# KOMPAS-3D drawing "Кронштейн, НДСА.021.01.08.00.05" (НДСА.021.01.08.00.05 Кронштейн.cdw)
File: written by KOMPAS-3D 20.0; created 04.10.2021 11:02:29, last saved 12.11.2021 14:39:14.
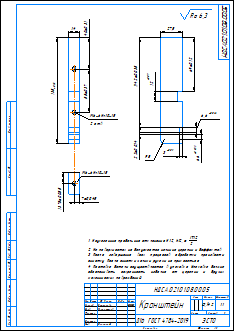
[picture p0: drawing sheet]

Sheet 1: A3, portrait

Document properties: Полное имя файла: C:\Users\korychko\Desktop\PLM\НДСА.021.01.08.00.05 Кронштейн.cdw; Автор: adminzsc; Параметр неуказанной шероховатости: Ra 6,3; PLM_CDWXDTO: <item xmlns="http://appius.ru/pdm" xmlns:xs="http://www.w3.org/2001/XMLSchema" xmlns:xsi="http://www.w3.org/2001/XMLSchema-instance" xsi:type="item">  <element xmlns:d2p1="http://v8.1c.ru/8.1/data/enterprise/current-config" xsi:type="d2p1:CatalogRef.aps_Элемен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; PDM_DOCXDTO: <item xmlns="http://appius.ru/pdm" xmlns:xs="http://www.w3.org/2001/XMLSchema" xmlns:xsi="http://www.w3.org/2001/XMLSchema-instance" xsi:type="item">  <element xmlns:d2p1="http://v8.1c.ru/8.1/data/enterprise/current-config" xsi:type="d2p1:CatalogRef.aps_Элемен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; PDM_ITEMXDTO: <item xmlns="http://appius.ru/pdm" xmlns:xs="http://www.w3.org/2001/XMLSchema" xmlns:xsi="http://www.w3.org/2001/XMLSchema-instance" xsi:type="item">  <element xmlns:d2p1="http://v8.1c.ru/8.1/data/enterprise/current-config" xsi:type="d2p1:CatalogRef.aps_Элемен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; Масса: 0.13847; PDM_DRAWINGXDTO: <item xmlns="http://appius.ru/pdm" xmlns:xs="http://www.w3.org/2001/XMLSchema" xmlns:xsi="http://www.w3.org/2001/XMLSchema-instance" xsi:type="item">  <element xmlns:d2p1="http://v8.1c.ru/8.1/data/enterprise/current-config" xsi:type="d2p1:CatalogRef.aps_Элемен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

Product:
- Part/product: Кронштейн  | designation НДСА.021.01.08.00.05
    Материал: Д16  ГОСТ 4784-2019 (density 2800 kg/m3)
    Масса: 0.138473
    additional columns: <item xmlns="http://appius.ru/pdm" xmlns:xs="http://www.w3.org/2001/XMLSchema" x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; <item xmlns="http://appius.ru/pdm" xmlns:xs="http://www.w3.org/2001/XMLSchema" x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; <item xmlns="http://appius.ru/pdm" xmlns:xs="http://www.w3.org/2001/XMLSchema" x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
    source file: НДСА.021.01.08.00.05 Кронштейн.cdw

Title block, sheet 1: Наименование: Кронштейн; designation: НДСА.021.01.08.00.05; Материал: Д16  ГОСТ 4784-2019; Масса: 0,14 г; Количество листов документа: 1; organisation: ЭСТО; Форматы листов документа: A3; stored path: C:\Users\vasilyeva\Desktop\PM_APPIUS\НДСА.021.01.08.00.05 Кронштейн.cdw; Разработал: Васильева; Проверил: Горностаев; Утвердил: Белецкий; Разработал, date: 04.10.2021

Views: Вид 1, Спереди, Проекционный вид 2, Проекционный вид 3
Referenced files in C:\Users\vasilyeva\Desktop\PM_APPIUS\: НДСА.021.01.08.00.05 Кронштейн.m3d
Referenced files in C:\Users\korychko\Desktop\PLM\: НДСА.021.01.08.00.05 Кронштейн.m3d
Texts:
  JS11
  Ra 6,3
  НДСА.021.01.08.00.05 Кронштейн
Dimensions and other numbers on the sheet: 14; 40±0,31; 55±0,37; 135; 27,5; 5; 12; 6,6; 69±0,12; 114,2±0,035; 3; 2,2±0,014; 13,75±0,055; 7±0,045; 2 отв.; 1:1; 1; 0,14 г; 04.10.2021

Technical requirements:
  Неуказанные предельные отклонения H12, h12,    IT12 2 .
  На поверхностях не допускается наличие царапин и деффектов.
  После завершения всех процессов обработки произвести
  очистку. После очистки голыми руками не прикосаться.
  Поставка детали осуществляется в упаковке. Упаковка должна
  обеспечивать сохранность изделия от царапин и других
  механических повреждений.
